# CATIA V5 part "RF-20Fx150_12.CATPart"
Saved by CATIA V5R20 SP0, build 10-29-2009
Part number: _RF-20Fx150
Definition: NONE
Nomenclature: _RF-20Fx150
Source: Unknown
Description: PART-_RF-20Fx150-DESC
Bounding box of the stored display mesh (mm): x -150 to 29.5, y -10.75 to 10.75, z -10.75 to 10.75
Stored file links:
  C:\Users\Utente\Desktop\IO LAVORO\3D X SITO CF\X SITO\PLASTICA\RFF\RF-20Fx150_12.CATPart

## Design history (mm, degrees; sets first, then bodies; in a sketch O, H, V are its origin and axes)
Body1 "_RF-20Fx150" (main body)
  Solid1: solid without history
